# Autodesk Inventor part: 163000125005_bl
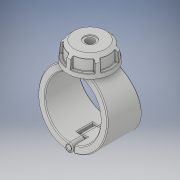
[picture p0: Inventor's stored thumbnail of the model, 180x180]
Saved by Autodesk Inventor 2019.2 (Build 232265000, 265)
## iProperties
Created: 2022-02
Part Number: 163000125005_bl
Material: Generic
Description: Plassadle Threaded 125x1/2''
Document SubType Name: Modeling
Designer: comp2
Density: 1 g/cm^3
Appearance: Default
Author: comp2
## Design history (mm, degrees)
derived "16300.ipt"
feature "Solid1::16300.ipt" dims "ScaleForDerivedMember" = 10
feature "Solid2::16300.ipt" dims "ScaleForDerivedMember" = 10
feature "Solid3::16300.ipt" dims "ScaleForDerivedMember" = 10
feature "Solid4::16300.ipt" dims "ScaleForDerivedMember" = 10
tag "TaggingFeature1"
body "Solid1"
body "Solid2"
body "Solid3"
body "Solid4"
other parameters: "d0" = 125 [user parameter], "d2" = 157 [user parameter], "d3" = 62.5 [user parameter], "d7" = 149.15 [user parameter], "d8" = 85 deg [user parameter], "d9" = 45 deg [user parameter], "d10" = 102 [user parameter], "d11" = 49 [user parameter], "d12" = 29.2495 [user parameter], "d13" = 42.84 [user parameter], "d14" = 27.9465 [user parameter], "d42" = 3.2 [user parameter], "d49" = 3.14 [user parameter], "d51" = 0 [user parameter], "d52" = 22.4 [user parameter], "d53" = 86.35 [user parameter], "d54" = 35 [user parameter], "d55" = 0 [user parameter], "d59" = 0 [user parameter], "d61" = 0 [user parameter], "d62" = 35 [user parameter], "d63" = 0 [user parameter], "d65" = 0 [user parameter], "d67" = 0 [user parameter], "d69" = 0 [user parameter], "d70" = 1 [user parameter], "d71" = 96 [user parameter], "d72" = 0 [user parameter], "d73" = 2 [user parameter], "d78" = 86.7 [user parameter], "d79" = 5.1 [user parameter], "d80" = 60 deg [user parameter], "d81" = 5.1 [user parameter], "d84" = 0 [user parameter], "d85" = 1 [user parameter], "d87" = 360 deg [user parameter], "d122" = 49 [user parameter], "d124" = 42.80128 [user parameter], "d125" = 2.08925 [user parameter], "d127" = 198 [user parameter], "d129" = 18.631 [user parameter], "d130" = 15.83635 [user parameter], "d131" = 31.85 [user parameter], "d132" = 45 deg [user parameter], "d133" = 22.295 [user parameter], "d134" = 9.3155 [user parameter], "d136" = 0 [user parameter], "d138" = 0 [user parameter], "d" = 125 [user parameter], "d1" = 25 [user parameter], "B" = 157 [user parameter], "E_" = 54 [user parameter], "E1" = 102 [user parameter], "H1" = 198 [user parameter], "H2" = 49 [user parameter], "H3" = 78 [user parameter], "H_costum" = 49 [user parameter], "Rp" = 18.631 [user parameter], "d128" = 41.785 [user parameter]
